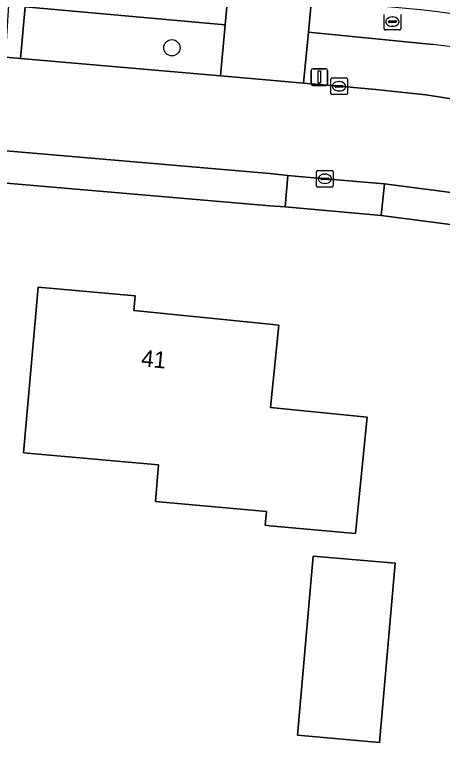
# Model space of a CAD drawing. Extents: x 162722 to 165104, y 384719 to 386284.
# Drawn here: x 163984.67 to 164010.37, y 385143.65 to 385187.32 of the extents above; entities that cross this region are included whole.
import ezdxf

# ---------------------------------------------------------------- set-up
doc = ezdxf.new("R2010")
doc.units = 0
for name, color, linetype in [('IMGEO_Boom', 7, 'Continuous'), ('IMGEO_Brandkraan', 7, 'Continuous'), ('IMGEO_Erf', 7, 'Continuous'), ('IMGEO_Groenvoorziening', 7, 'Continuous'), ('IMGEO_Kolk', 7, 'Continuous'), ('IMGEO_Lichtmast', 7, 'Continuous'), ('IMGEO_Pand', 7, 'Continuous'), ('IMGEO_Pand_nummerreeks', 7, 'Continuous'), ('IMGEO_Parkeervlak_open', 7, 'Continuous'), ('IMGEO_Rijbaan_lokaal_gesloten', 7, 'Continuous'), ('IMGEO_Voetpad_open', 7, 'Continuous')]:
    doc.layers.add(name, color=color, linetype=linetype)

msp = doc.modelspace()

# ---------------------------------------------------------------- linework, layer by layer
at = {"layer": 'IMGEO_Boom'}
msp.add_circle((163994.12, 385185.325), 0.489, dxfattribs=at)
at = {"layer": 'IMGEO_Brandkraan'}
for p, q in [((164006.863, 385186.466), (164006.863, 385187.318)), ((164007.864, 385187.318), (164007.864, 385186.466)), ((164007.122, 385186.886), (164007.122, 385186.898)), ((164007.56, 385186.849), (164007.162, 385186.849)), ((164007.165, 385186.935), (164007.563, 385186.935)), ((164007.351, 385187.172), (164007.376, 385187.172)), ((164007.606, 385186.898), (164007.606, 385186.886)), ((164007.79, 385186.392), (164006.938, 385186.392)), ((164007.374, 385186.612), (164007.349, 385186.612))]:
    msp.add_line(p, q, dxfattribs=at)
for points in [[(164006.863, 385186.466), (164006.863, 385187.318)], [(164007.864, 385187.318), (164007.864, 385186.466)], [(164007.79, 385186.392), (164006.938, 385186.392)]]:
    msp.add_lwpolyline(points, dxfattribs=at)
for centre, radius, start, end in [((164007.162, 385186.895), 0.0403, 85.8775, 175.7526), ((164007.159, 385186.885), 0.0366, 178.938, 274.7102), ((164007.563, 385186.892), 0.043, 264.8664, 352.4533), ((164007.567, 385186.897), 0.0386, 1.7309, 96.639), ((164006.94, 385186.468), 0.0765, 181.552, 268.448), ((164006.94, 385186.468), 0.0765, 181.552, 268.448), ((164007.788, 385186.468), 0.0765, 271.552, 358.448), ((164007.788, 385186.468), 0.0765, 271.552, 358.448)]:
    msp.add_arc(centre, radius, start, end, dxfattribs=at)
for centre, major_axis, ratio, start_param, end_param in [((164007.35, 385186.892), (-0.387, 0.002), 0.722429, 4.712389, 7.853982), ((164007.375, 385186.892), (-0.39, 0.002), 0.717154, 1.570796, 4.712389)]:
    msp.add_ellipse(centre, major_axis=major_axis, ratio=ratio, start_param=start_param, end_param=end_param, dxfattribs=at)
at = {"layer": 'IMGEO_Erf'}
msp.add_lwpolyline([(164019.273, 385173.042), (164011.601, 385174.616), (164006.685, 385175.256), (164000.92, 385175.782), (164000, 385175.844), (163980.454, 385177.525), (163975.738, 385178.054), (163957.036, 385179.674)], dxfattribs=at)
for points in [[(163999.799, 385157.513), (163993.131, 385158.112), (163993.327, 385160.298), (163985.208, 385161.028), (163985.654, 385165.99), (163986.101, 385170.969), (163991.921, 385170.446), (163991.842, 385169.561), (164000, 385168.741), (164000.546, 385168.686), (164000.046, 385163.745), (164005.853, 385163.162), (164005.353, 385158.188), (164005.151, 385156.183), (164000, 385156.652), (163999.725, 385156.677)], [(164001.662, 385144.082), (164002.611, 385154.833), (164007.53, 385154.399), (164006.58, 385143.648)]]:
    msp.add_lwpolyline(points, close=True, dxfattribs=at)
msp.add_arc((163996.852, 385075.903), 112.353, 69.49693, 83.76696, dxfattribs=at)
at = {"layer": 'IMGEO_Groenvoorziening'}
msp.add_lwpolyline([(163997.313, 385186.71), (163985.32, 385187.783), (163985.03, 385184.687), (163997.041, 385183.651)], close=True, dxfattribs=at)
msp.add_lwpolyline([(164009.796, 385185.514), (164002.32, 385186.259), (164002.022, 385183.193), (164004.157, 385183.013), (164006.361, 385182.82), (164009.373, 385182.493), (164014.356, 385181.719), (164024.328, 385179.48), (164034.061, 385176.359), (164035.388, 385179.326)], dxfattribs=at)
msp.add_arc((163997.66, 385079.307), 106.898, 69.33302, 83.48118, dxfattribs=at)
at = {"layer": 'IMGEO_Kolk'}
for p, q in [((164003.656, 385182.587), (164003.656, 385183.439)), ((164003.731, 385183.513), (164004.583, 385183.513)), ((164004.144, 385183.293), (164004.169, 385183.293)), ((164004.657, 385183.439), (164004.657, 385182.587)), ((164003.915, 385183.007), (164003.915, 385183.019)), ((164004.353, 385182.97), (164003.955, 385182.97)), ((164003.958, 385183.056), (164004.356, 385183.056)), ((164004.399, 385183.019), (164004.399, 385183.007)), ((164004.583, 385182.513), (164003.731, 385182.513)), ((164004.167, 385182.733), (164004.142, 385182.733)), ((164002.805, 385177.038), (164002.805, 385177.89)), ((164002.88, 385177.964), (164003.732, 385177.964)), ((164003.293, 385177.744), (164003.318, 385177.744)), ((164003.806, 385177.89), (164003.806, 385177.038)), ((164003.064, 385177.458), (164003.064, 385177.47)), ((164003.502, 385177.421), (164003.104, 385177.421)), ((164003.107, 385177.507), (164003.505, 385177.507)), ((164003.316, 385177.184), (164003.291, 385177.184)), ((164003.548, 385177.47), (164003.548, 385177.458)), ((164003.732, 385176.964), (164002.88, 385176.964))]:
    msp.add_line(p, q, dxfattribs=at)
for points in [[(164003.656, 385182.587), (164003.656, 385183.439)], [(164003.731, 385183.513), (164004.583, 385183.513)], [(164004.657, 385183.439), (164004.657, 385182.587)], [(164004.583, 385182.513), (164003.731, 385182.513)], [(164002.805, 385177.038), (164002.805, 385177.89)], [(164002.88, 385177.964), (164003.732, 385177.964)], [(164003.806, 385177.89), (164003.806, 385177.038)], [(164003.732, 385176.964), (164002.88, 385176.964)]]:
    msp.add_lwpolyline(points, dxfattribs=at)
for centre, radius, start, end in [((164003.733, 385183.437), 0.0765, 91.552, 178.448), ((164003.733, 385183.437), 0.0765, 91.552, 178.448), ((164004.581, 385183.437), 0.0765, 1.552, 88.448), ((164004.581, 385183.437), 0.0765, 1.552, 88.448), ((164003.955, 385183.016), 0.0403, 85.8775, 175.7526), ((164003.952, 385183.006), 0.0366, 178.938, 274.7102), ((164004.356, 385183.013), 0.043, 264.8664, 352.4533), ((164004.36, 385183.018), 0.0386, 1.7309, 96.639), ((164003.733, 385182.589), 0.0765, 181.552, 268.448), ((164003.733, 385182.589), 0.0765, 181.552, 268.448), ((164004.581, 385182.589), 0.0765, 271.552, 358.448), ((164004.581, 385182.589), 0.0765, 271.552, 358.448), ((164002.882, 385177.888), 0.0765, 91.552, 178.448), ((164002.882, 385177.888), 0.0765, 91.552, 178.448), ((164003.73, 385177.888), 0.0765, 1.552, 88.448), ((164003.73, 385177.888), 0.0765, 1.552, 88.448), ((164003.104, 385177.467), 0.0403, 85.8775, 175.7526), ((164003.101, 385177.457), 0.0366, 178.938, 274.7102), ((164003.505, 385177.464), 0.043, 264.8664, 352.4533), ((164003.509, 385177.469), 0.0386, 1.7309, 96.639), ((164002.882, 385177.04), 0.0765, 181.552, 268.448), ((164002.882, 385177.04), 0.0765, 181.552, 268.448), ((164003.73, 385177.04), 0.0765, 271.552, 358.448), ((164003.73, 385177.04), 0.0765, 271.552, 358.448)]:
    msp.add_arc(centre, radius, start, end, dxfattribs=at)
for centre, major_axis, ratio, start_param, end_param in [((164004.143, 385183.013), (-0.387, 0.002), 0.722429, 4.712389, 7.853982), ((164004.168, 385183.013), (-0.39, 0.002), 0.717154, 1.570796, 4.712389), ((164003.292, 385177.464), (-0.387, 0.002), 0.722429, 4.712389, 7.853982), ((164003.317, 385177.464), (-0.39, 0.002), 0.717154, 1.570796, 4.712389)]:
    msp.add_ellipse(centre, major_axis=major_axis, ratio=ratio, start_param=start_param, end_param=end_param, dxfattribs=at)
at = {"layer": 'IMGEO_Lichtmast'}
for p, q in [((164002.482, 385183.171), (164002.482, 385183.971)), ((164002.482, 385183.971), (164002.482, 385183.171)), ((164002.582, 385184.071), (164003.372, 385184.071)), ((164003.372, 385184.071), (164002.582, 385184.071)), ((164003.472, 385183.971), (164003.472, 385183.171)), ((164003.472, 385183.171), (164003.472, 385183.971)), ((164003.372, 385183.071), (164002.582, 385183.071)), ((164002.582, 385183.071), (164003.372, 385183.071))]:
    msp.add_line(p, q, dxfattribs=at)
msp.add_lwpolyline([(164002.902, 385183.946), (164003.052, 385183.946), (164003.052, 385183.196), (164002.902, 385183.196), (164002.902, 385183.946)], dxfattribs=at)
for centre, start, end in [((164002.582, 385183.971), 90, 180), ((164002.582, 385183.971), 90, 180), ((164003.372, 385183.971), 0, 90), ((164003.372, 385183.971), 360, 90), ((164002.582, 385183.171), 180, 270), ((164002.582, 385183.171), 180, 270), ((164003.372, 385183.171), 270, 0), ((164003.372, 385183.171), 270, 0)]:
    msp.add_arc(centre, 0.1, start, end, dxfattribs=at)
at = {"layer": 'IMGEO_Pand'}
for points in [[(164005.353, 385158.188), (164005.853, 385163.162), (164000.046, 385163.745), (164000.546, 385168.686), (164000, 385168.741), (163991.842, 385169.561), (163991.921, 385170.446), (163986.101, 385170.969), (163985.654, 385165.99), (163985.208, 385161.028), (163993.327, 385160.298), (163993.131, 385158.112), (163999.799, 385157.513), (163999.725, 385156.677), (164000, 385156.652), (164005.151, 385156.183)], [(164001.662, 385144.082), (164006.58, 385143.648), (164007.53, 385154.399), (164002.611, 385154.833)]]:
    msp.add_lwpolyline(points, close=True, dxfattribs=at)
at = {"layer": 'IMGEO_Parkeervlak_open'}
for points in [[(163980.454, 385177.525), (164000, 385175.844), (164000.92, 385175.782), (164001.089, 385177.667), (164000, 385177.774), (163982.043, 385179.328), (163980.657, 385179.445)], [(164006.685, 385175.256), (164011.601, 385174.616), (164019.273, 385173.042), (164019.703, 385174.889), (164011.653, 385176.534), (164006.878, 385177.162)]]:
    msp.add_lwpolyline(points, close=True, dxfattribs=at)
at = {"layer": 'IMGEO_Rijbaan_lokaal_gesloten'}
for points in [[(164069.537, 385160.271), (164053.648, 385167.548), (164050.878, 385168.812), (164049.034, 385169.655), (164038.924, 385174.279), (164037.91, 385174.757), (164034.061, 385176.359), (164024.328, 385179.48), (164014.356, 385181.719), (164009.373, 385182.493), (164006.361, 385182.82), (164004.157, 385183.013), (164002.022, 385183.193), (164000, 385183.379), (163997.041, 385183.651), (163985.03, 385184.687), (163984.115, 385184.765), (163982.729, 385184.885), (163961.332, 385186.712), (163953.03, 385187.504), (163948.264, 385187.936), (163942.935, 385188.388), (163927.518, 385189.855), (163916.96, 385190.797)], [(163946.345, 385182.337), (163959.871, 385181.283), (163961.537, 385181.086), (163975.917, 385179.858), (163980.657, 385179.445), (163982.043, 385179.328), (164000, 385177.774), (164001.089, 385177.667), (164003.306, 385177.464), (164006.878, 385177.162), (164011.653, 385176.534), (164019.703, 385174.889), (164019.892, 385174.859), (164021.592, 385174.502), (164023.254, 385173.995), (164026.265, 385173.125), (164031.751, 385171.269), (164036.795, 385169.137), (164051.9, 385162.23), (164052.042, 385162.153), (164054.177, 385161.165), (164066.085, 385155.714)]]:
    msp.add_lwpolyline(points, dxfattribs=at)
at = {"layer": 'IMGEO_Voetpad_open'}
for points in [[(163997.313, 385186.71), (163997.498, 385188.685), (163953.489, 385192.612), (163953.324, 385190.647), (163984.32, 385187.873), (163984.115, 385184.765), (163985.03, 385184.687), (163985.32, 385187.783)], [(164000, 385183.379), (164002.022, 385183.193), (164002.32, 385186.259), (164002.51, 385188.217), (164000, 385188.451), (163997.498, 385188.685), (163997.313, 385186.71), (163997.041, 385183.651)], [(164000.92, 385175.782), (164006.685, 385175.256), (164006.878, 385177.162), (164003.306, 385177.464), (164001.089, 385177.667)]]:
    msp.add_lwpolyline(points, close=True, dxfattribs=at)
msp.add_lwpolyline([(164009.05, 385187.592), (164002.51, 385188.217), (164002.32, 385186.259), (164009.796, 385185.514)], dxfattribs=at)
for centre, radius, start, end in [((163996.852, 385075.903), 112.353, 69.49693, 83.76696), ((163997.66, 385079.307), 106.898, 69.33302, 83.48118)]:
    msp.add_arc(centre, radius, start, end, dxfattribs=at)

# ---------------------------------------------------------------- texts
at = {"layer": 'IMGEO_Pand_nummerreeks'}
msp.add_text('41', height=1, rotation=354.2597, dxfattribs=at).set_placement((163992.248, 385166.223))

doc.saveas('drawing.dxf')
